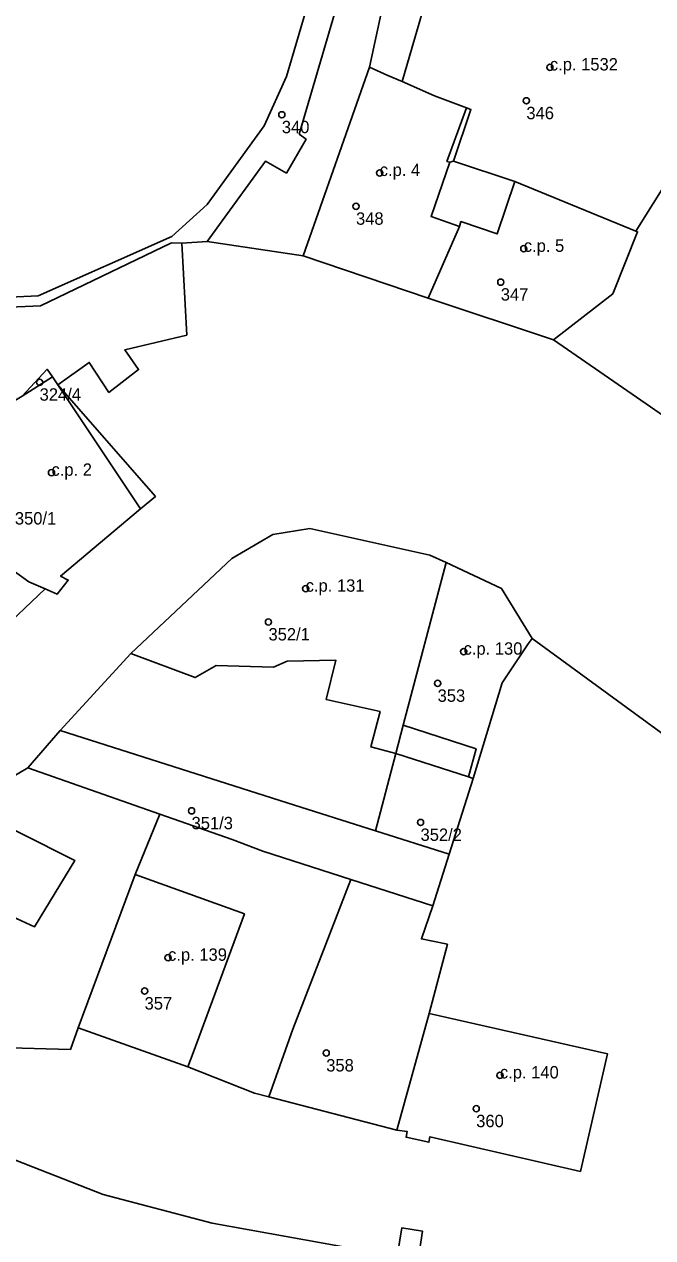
# Model space of a CAD drawing. Extents: x -878211 to -870363, y -1058464 to -1052522.
# Drawn here: x -874670.5 to -874619.7, y -1056247.4 to -1056149.3 of the extents above; entities that cross this region are included whole.
import ezdxf

# ---------------------------------------------------------------- set-up
doc = ezdxf.new("R2010")
doc.units = 0
for name, color, linetype in [('Definiční body', 7, 'Continuous'), ('Polygon budovy', 7, 'Continuous'), ('Polygon parcely', 7, 'Continuous')]:
    doc.layers.add(name, color=color, linetype=linetype)

msp = doc.modelspace()

# ---------------------------------------------------------------- linework, layer by layer
at = {"layer": 'Definiční body'}
for centre in [(-874628.03, -1056152.81994), (-874629.93, -1056155.51994), (-874649.71, -1056156.64994), (-874641.79, -1056161.34994), (-874643.71, -1056164.04994), (-874630.14, -1056167.47994), (-874632, -1056170.17994), (-874669.3, -1056178.26994), (-874668.34, -1056185.57994), (-874647.78, -1056194.94994), (-874650.79, -1056197.64994), (-874635.01, -1056200.03994), (-874637.11, -1056202.60994), (-874657.01, -1056212.90994), (-874638.49, -1056213.84994), (-874658.91, -1056224.77994), (-874660.81, -1056227.47994), (-874646.12, -1056232.48994), (-874632.07, -1056234.28994), (-874633.99, -1056236.98994)]:
    msp.add_circle(centre, 0.25, dxfattribs=at)
at = {"layer": 'Polygon budovy'}
for points in [[(-874636.94, -1056143.49), (-874639.98, -1056153.97), (-874637.37, -1056155.11), (-874634.78, -1056156.1), (-874634.42, -1056156.22), (-874635.82, -1056160.39), (-874630.86, -1056162.05), (-874621.07, -1056166.06), (-874615.34, -1056156.9), (-874614.48, -1056157.42), (-874612.31, -1056153.94), (-874613.1, -1056153.4), (-874610.56, -1056149.13), (-874611.07, -1056148.65), (-874610.81, -1056148.2), (-874622.97, -1056145.04), (-874623.36, -1056146.54), (-874624.83, -1056146.16), (-874631.09, -1056144.49), (-874631.48, -1056143.36), (-874634.36, -1056143.27)], [(-874647.99, -1056168.05), (-874637.88, -1056171.46), (-874635.35, -1056165.67), (-874637.64, -1056164.88), (-874636.13, -1056160.48), (-874636.36, -1056160.42), (-874634.78, -1056156.1), (-874637.37, -1056155.11), (-874639.98, -1056153.97), (-874641.13, -1056153.47), (-874642.62, -1056152.79)], [(-874635.35, -1056165.67), (-874637.88, -1056171.46), (-874627.74, -1056174.84), (-874622.94, -1056171.12), (-874620.94, -1056166.11), (-874621.07, -1056166.06), (-874630.86, -1056162.05), (-874632.28, -1056166.28), (-874635.22, -1056165.29)], [(-874677.98, -1056183.76), (-874676.72, -1056185.93), (-874676.32, -1056186.62), (-874672.23, -1056192.57), (-874674.22, -1056194.63), (-874673.33, -1056195.4), (-874671.43, -1056193.49), (-874670.18, -1056194.41), (-874668.85, -1056194.96), (-874667.89, -1056195.41), (-874666.98, -1056194.26), (-874667.6, -1056193.93), (-874661.14, -1056188.51), (-874667.82, -1056178.48), (-874668.25, -1056177.84), (-874670.71, -1056179.4)], [(-874636.42, -1056192.83), (-874637.73, -1056192.25), (-874647.44, -1056190.1), (-874650.45, -1056190.57), (-874653.75, -1056192.52), (-874661.93, -1056200.2), (-874656.72, -1056202.14), (-874655.03, -1056201.17), (-874650.38, -1056201.3), (-874649.28, -1056200.82), (-874645.33, -1056200.74), (-874646.13, -1056203.9), (-874641.76, -1056204.88), (-874642.51, -1056207.75), (-874640.5, -1056208.27), (-874639.9, -1056206)], [(-874634.6, -1056210.17), (-874634.23, -1056210.29), (-874631.89, -1056202.56), (-874629.78, -1056199.42), (-874629.47, -1056198.99), (-874631.94, -1056194.93), (-874636.42, -1056192.83), (-874639.9, -1056206), (-874634, -1056207.9)], [(-874675.38, -1056212.44), (-874687.96, -1056222.51), (-874687.74, -1056224.74), (-874681.17, -1056228.78), (-874675.44, -1056231.54), (-874672.71, -1056232.05), (-874671.64, -1056228.75), (-874677.55, -1056225.92), (-874671.81, -1056221.33), (-874669.72, -1056222.29), (-874666.44, -1056216.93)], [(-874661.58, -1056218.05), (-874666.17, -1056230.46), (-874657.31, -1056233.59), (-874656.87, -1056232.47), (-874652.74, -1056221.24)], [(-874640.42, -1056238.71), (-874639.57, -1056238.84), (-874639.66, -1056239.29), (-874637.82, -1056239.7), (-874637.73, -1056239.26), (-874625.56, -1056242.05), (-874623.38, -1056232.54), (-874637.78, -1056229.29)]]:
    msp.add_lwpolyline(points, close=True, dxfattribs=at)
at = {"layer": 'Polygon parcely'}
for points in [[(-874679.26, -1056172.52), (-874669.23, -1056172.08), (-874658.62, -1056166.99), (-874657.81, -1056167.03), (-874655.74, -1056166.89), (-874651.04, -1056160.41), (-874649.34, -1056161.36), (-874647.75, -1056158.63), (-874648.3, -1056158.21), (-874645.44, -1056148.49), (-874644.01, -1056133.39), (-874647.89, -1056122.39), (-874655.23, -1056109.84), (-874669.65, -1056092.09), (-874691.09, -1056082.27)], [(-874693.28, -1056083.81), (-874670.53, -1056093.92), (-874656.5, -1056111.27), (-874649.47, -1056124.07), (-874646.39, -1056132.5), (-874646.59, -1056140.87), (-874647.54, -1056147.52), (-874649.33, -1056153.56), (-874651.13, -1056157.54), (-874655.74, -1056163.9), (-874658.61, -1056166.48), (-874669.43, -1056171.29), (-874679.22, -1056171.74)], [(-874679.22, -1056171.74), (-874669.43, -1056171.29), (-874658.61, -1056166.48), (-874655.74, -1056163.9), (-874651.13, -1056157.54), (-874649.33, -1056153.56), (-874647.54, -1056147.52), (-874646.59, -1056140.87), (-874646.39, -1056132.5), (-874649.47, -1056124.07), (-874656.5, -1056111.27), (-874670.53, -1056093.92), (-874693.28, -1056083.81)], [(-874610.56, -1056149.13), (-874613.1, -1056153.4), (-874612.31, -1056153.94), (-874614.48, -1056157.42), (-874615.34, -1056156.9), (-874621.07, -1056166.06), (-874620.94, -1056166.11), (-874622.94, -1056171.12), (-874627.74, -1056174.84), (-874618.42, -1056181.27), (-874615.08, -1056173.03), (-874612.77, -1056173.34), (-874612.52, -1056171.04), (-874606.57, -1056171.84), (-874605.16, -1056159.85), (-874602.18, -1056160.2), (-874601.46, -1056154.13), (-874582.77, -1056130.09)], [(-874640.68, -1056143.81), (-874642.62, -1056152.79), (-874641.13, -1056153.47), (-874639.98, -1056153.97), (-874637.37, -1056155.11), (-874634.78, -1056156.1), (-874634.42, -1056156.22), (-874635.82, -1056160.39), (-874630.86, -1056162.05), (-874621.07, -1056166.06), (-874615.34, -1056156.9), (-874614.48, -1056157.42), (-874612.31, -1056153.94), (-874613.1, -1056153.4), (-874610.56, -1056149.13)], [(-874670.71, -1056179.4), (-874668.7, -1056177.22), (-874668.25, -1056177.84), (-874667.82, -1056178.48), (-874665.29, -1056176.66), (-874663.69, -1056179.09), (-874661.29, -1056177.25), (-874662.41, -1056175.65), (-874657.4, -1056174.46), (-874657.81, -1056167.03), (-874658.62, -1056166.99), (-874669.23, -1056172.08), (-874679.26, -1056172.52)], [(-874618.42, -1056181.27), (-874627.74, -1056174.84), (-874637.88, -1056171.46), (-874647.99, -1056168.05), (-874655.74, -1056166.89), (-874657.81, -1056167.03), (-874657.4, -1056174.46), (-874662.41, -1056175.65), (-874661.29, -1056177.25), (-874663.69, -1056179.09), (-874665.29, -1056176.66), (-874667.82, -1056178.48), (-874659.94, -1056187.5), (-874661.14, -1056188.51), (-874667.6, -1056193.93), (-874666.98, -1056194.26), (-874667.89, -1056195.41), (-874668.85, -1056194.96), (-874672.74, -1056198.62)], [(-874675.38, -1056212.44), (-874670.25, -1056209.43), (-874667.64, -1056206.43), (-874661.93, -1056200.2), (-874653.75, -1056192.52), (-874650.45, -1056190.57), (-874647.44, -1056190.1), (-874637.73, -1056192.25), (-874636.42, -1056192.83), (-874631.94, -1056194.93), (-874629.47, -1056198.99), (-874615.67, -1056209.05), (-874605.29, -1056213.73), (-874601.61, -1056215.84), (-874600.55, -1056216.63), (-874581.11, -1056219.33), (-874570.1, -1056218.77), (-874558.48, -1056215.79), (-874545.18, -1056211.72), (-874543.73, -1056211.28)], [(-874615.67, -1056209.05), (-874629.47, -1056198.99), (-874629.78, -1056199.42), (-874631.89, -1056202.56), (-874634.23, -1056210.29), (-874636.17, -1056216.42), (-874637.5, -1056220.6), (-874638.42, -1056223.26), (-874637.64, -1056223.42), (-874636.32, -1056223.69), (-874637.78, -1056229.29), (-874623.38, -1056232.54), (-874625.56, -1056242.05), (-874637.73, -1056239.26), (-874637.82, -1056239.7), (-874639.66, -1056239.29), (-874639.57, -1056238.84), (-874640.42, -1056238.71), (-874650.76, -1056236.04), (-874651.92, -1056235.72), (-874657.31, -1056233.59), (-874666.17, -1056230.46), (-874666.81, -1056232.19), (-874672.71, -1056232.05)], [(-874672.49, -1056240.67), (-874664.15, -1056243.93), (-874655.34, -1056246.24), (-874640.39, -1056248.94), (-874640, -1056246.61), (-874638.34, -1056246.88), (-874638.69, -1056249.19)], [(-874543.06, -1056286.68), (-874545.12, -1056280.87), (-874546.44, -1056278.17), (-874548.18, -1056275.69), (-874552.52, -1056271.38), (-874557.43, -1056267.84), (-874565.58, -1056264.06), (-874569.92, -1056262.48), (-874571.26, -1056261.99), (-874585.56, -1056257.77), (-874591.42, -1056256.46), (-874609.18, -1056253.51), (-874638.69, -1056249.19), (-874638.34, -1056246.88), (-874640, -1056246.61), (-874640.39, -1056248.94), (-874655.34, -1056246.24), (-874664.15, -1056243.93), (-874672.49, -1056240.67)]]:
    msp.add_lwpolyline(points, dxfattribs=at)
for points in [[(-874653.95, -1056105.43), (-874654.62, -1056104.57), (-874655.08, -1056104.14), (-874658.22, -1056100.23), (-874668.09, -1056088.87), (-874669.65, -1056092.09), (-874655.23, -1056109.84), (-874647.89, -1056122.39), (-874644.01, -1056133.39), (-874645.44, -1056148.49), (-874648.3, -1056158.21), (-874647.75, -1056158.63), (-874649.34, -1056161.36), (-874651.04, -1056160.41), (-874655.74, -1056166.89), (-874647.99, -1056168.05), (-874642.62, -1056152.79), (-874640.68, -1056143.81), (-874640.55, -1056131.83), (-874644.97, -1056114.7)], [(-874647.99, -1056168.05), (-874637.88, -1056171.46), (-874635.35, -1056165.67), (-874637.64, -1056164.88), (-874636.13, -1056160.48), (-874635.82, -1056160.39), (-874634.42, -1056156.22), (-874634.78, -1056156.1), (-874637.37, -1056155.11), (-874639.98, -1056153.97), (-874641.13, -1056153.47), (-874642.62, -1056152.79)], [(-874636.13, -1056160.48), (-874637.64, -1056164.88), (-874635.35, -1056165.67), (-874637.88, -1056171.46), (-874627.74, -1056174.84), (-874622.94, -1056171.12), (-874620.94, -1056166.11), (-874621.07, -1056166.06), (-874630.86, -1056162.05), (-874635.82, -1056160.39)], [(-874668.25, -1056177.84), (-874668.7, -1056177.22), (-874670.71, -1056179.4)], [(-874668.85, -1056194.96), (-874667.89, -1056195.41), (-874666.98, -1056194.26), (-874667.6, -1056193.93), (-874661.14, -1056188.51), (-874659.94, -1056187.5), (-874667.82, -1056178.48), (-874668.25, -1056177.84), (-874670.71, -1056179.4), (-874677.98, -1056183.76), (-874676.72, -1056185.93), (-874680.13, -1056191), (-874676.24, -1056195.34), (-874672.74, -1056198.62)], [(-874636.42, -1056192.83), (-874637.73, -1056192.25), (-874647.44, -1056190.1), (-874650.45, -1056190.57), (-874653.75, -1056192.52), (-874661.93, -1056200.2), (-874667.64, -1056206.43), (-874649.29, -1056212.26), (-874642.13, -1056214.53), (-874640.5, -1056208.27), (-874639.9, -1056206)], [(-874629.47, -1056198.99), (-874631.94, -1056194.93), (-874636.42, -1056192.83), (-874639.9, -1056206), (-874640.5, -1056208.27), (-874634.6, -1056210.17), (-874634.23, -1056210.29), (-874631.89, -1056202.56), (-874629.78, -1056199.42)], [(-874644.13, -1056218.46), (-874637.5, -1056220.6), (-874636.17, -1056216.42), (-874642.13, -1056214.53), (-874649.29, -1056212.26), (-874667.64, -1056206.43), (-874670.25, -1056209.43), (-874659.58, -1056213.18), (-874653.74, -1056215.23), (-874651.24, -1056216.16)], [(-874634.6, -1056210.17), (-874640.5, -1056208.27), (-874642.13, -1056214.53), (-874636.17, -1056216.42), (-874634.23, -1056210.29)], [(-874672.71, -1056232.05), (-874666.81, -1056232.19), (-874666.17, -1056230.46), (-874661.58, -1056218.05), (-874659.58, -1056213.18), (-874670.25, -1056209.43), (-874675.38, -1056212.44), (-874687.96, -1056222.51), (-874687.74, -1056224.74), (-874681.17, -1056228.78), (-874675.44, -1056231.54)], [(-874644.13, -1056218.46), (-874651.24, -1056216.16), (-874653.74, -1056215.23), (-874659.58, -1056213.18), (-874661.58, -1056218.05), (-874666.17, -1056230.46), (-874657.31, -1056233.59), (-874651.92, -1056235.72), (-874650.76, -1056236.04), (-874648.81, -1056230.57), (-874646.15, -1056223.68)], [(-874637.78, -1056229.29), (-874636.32, -1056223.69), (-874637.64, -1056223.42), (-874638.42, -1056223.26), (-874637.5, -1056220.6), (-874644.13, -1056218.46), (-874646.15, -1056223.68), (-874648.81, -1056230.57), (-874650.76, -1056236.04), (-874640.42, -1056238.71)], [(-874640.42, -1056238.71), (-874639.57, -1056238.84), (-874639.66, -1056239.29), (-874637.82, -1056239.7), (-874637.73, -1056239.26), (-874625.56, -1056242.05), (-874623.38, -1056232.54), (-874637.78, -1056229.29)]]:
    msp.add_lwpolyline(points, close=True, dxfattribs=at)

# ---------------------------------------------------------------- texts
at = {"layer": 'Definiční body'}
for s, p in [('c.p. 1532', (-874628.03, -1056153.07)), ('346', (-874629.93, -1056157.009)), ('340', (-874649.71, -1056158.139)), ('c.p. 4', (-874641.79, -1056161.6)), ('348', (-874643.71, -1056165.539)), ('c.p. 5', (-874630.14, -1056167.73)), ('347', (-874632, -1056171.669)), ('324/4', (-874669.3, -1056179.759)), ('c.p. 2', (-874668.34, -1056185.83)), ('350/1', (-874671.3, -1056189.769)), ('c.p. 131', (-874647.78, -1056195.2)), ('352/1', (-874650.79, -1056199.139)), ('c.p. 130', (-874635.01, -1056200.29)), ('353', (-874637.11, -1056204.099)), ('351/3', (-874657.01, -1056214.399)), ('352/2', (-874638.49, -1056215.339)), ('c.p. 139', (-874658.91, -1056225.03)), ('357', (-874660.81, -1056228.969)), ('358', (-874646.12, -1056233.979)), ('c.p. 140', (-874632.07, -1056234.54)), ('360', (-874633.99, -1056238.479))]:
    msp.add_text(s, height=0.999996, dxfattribs=at).set_placement(p)

doc.saveas('drawing.dxf')
